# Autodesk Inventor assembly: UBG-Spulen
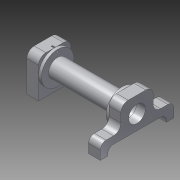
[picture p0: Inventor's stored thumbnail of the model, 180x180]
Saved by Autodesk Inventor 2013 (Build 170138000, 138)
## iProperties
Created: 2012-07
Part Number: UBG-Spulen
Document SubType Name: Assembly
Designer: rYan
Mass: 28.9805 g
Surface Area: 105.153 cm^2
Volume: 11.9369 cm^3
Density: 2.42781 g/cm^3
Author: rYan
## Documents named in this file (4)
- D:\SVN\2013\Inventor\Kicker\UBG-Spulen.iam
- D:\SVN\2013\Inventor\Kicker\Spulenhalter.ipt
- D:\SVN\2013\Inventor\Kicker\Straight Spulenkoerper.ipt
- D:\SVN\2013\Inventor\Kicker\Spulenhalter Vorne.ipt
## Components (3 placed, 3 different names)
1. Spulenhalter:1 — Passend:2, Passend:4, Winkel:1
2. Straight Spulenkörper:2 — Passend:2, Passend:4, Passend:5, Passend:6
3. Spulenhalter Vorne:1 — Passend:5, Passend:6, Winkel:1
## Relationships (5: Mate 4, Angle 1)
- Passend:2 [Mate]: Spulenhalter:1 ↔ Straight Spulenkörper:2
- Passend:4 [Mate]: Spulenhalter:1 ↔ Straight Spulenkörper:2
- Passend:5 [Mate]: Straight Spulenkörper:2 ↔ Spulenhalter Vorne:1
- Passend:6 [Mate]: Straight Spulenkörper:2 ↔ Spulenhalter Vorne:1
- Winkel:1 [Angle]: Spulenhalter:1 ↔ Spulenhalter Vorne:1
